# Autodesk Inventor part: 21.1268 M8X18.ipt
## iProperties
Created: 2006-02
Part Number: 21.1268 M8X18.ipt
Material: Steel, Mild
Description: Cylinder Head Cap Screw
Document SubType Name: Modeling
Standard: DIN 7984
Designer: Andy Moles
Standards Organization: DIN
Language: en-US
Size Designation: M8 x 20
Categories: <MemberInstance><Categories><Category DisplayName="Fasteners" InternalName="e4da775c-781d-43d5-af7c-5136215cf5a6" Mnemonic="FSTN"><Category DisplayName="Bolts"
Mass: 12.263 g
Surface Area: 10.1767 cm^2
Volume: 1.56018 cm^3
Density: 7.86 g/cm^3
Author: Andy Moles
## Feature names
1. Body [Revolution]
2. Slot [Extrusion]
3. Fillet1
4. Chamfer1
